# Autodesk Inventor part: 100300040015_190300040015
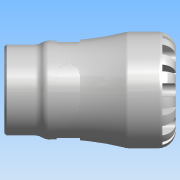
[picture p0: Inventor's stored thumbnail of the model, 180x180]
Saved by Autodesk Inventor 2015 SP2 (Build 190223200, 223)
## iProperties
Created: 2016-12
Part Number: 100300040015_190300040015
Material: PVC-Piping
Description: PLASSON FEMALE ADAPTOR 40X1.1/2" SERIES 1
Document SubType Name: Modeling
Designer: KIM
Mass: 664.223 g
Surface Area: 733.008 cm^2
Volume: 474.445 cm^3
Density: 1.4 g/cm^3
Appearance: Smooth - White
Author: KIM
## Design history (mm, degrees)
derived "1003.ipt"
feature "Solid1::1003.ipt"
tag "TaggingFeature1"
body "Solid1"
other parameters: "d0" = 103, "d1" = 29.4, "d8" = 59.5, "d13" = 8, "d14" = 8, "d15" = 0, "d17" = 360 deg, "d19" = 8 deg, "d20" = 0.8, "d21" = 0.8, "d22" = 8 deg, "d24" = 0, "d26" = 360 deg, "d32" = 7, "d33" = 7, "d39" = 1.34535, "d42" = 44.845, "d43" = 54.6, "d46" = 3.33333, "d47" = 24, "d48" = 42.60275, "d50" = 2.97, "d51" = 0.7, "d54" = 14, "d55" = 8.8, "d57" = 15.68, "d58" = 0, "d68" = 360 deg, "d72" = 0.8, "d74" = 0, "d76" = 11.9, "H_" = 103, "Rp" = 44.845, "l_2" = 24, "d9" = 10, "d49" = 9
